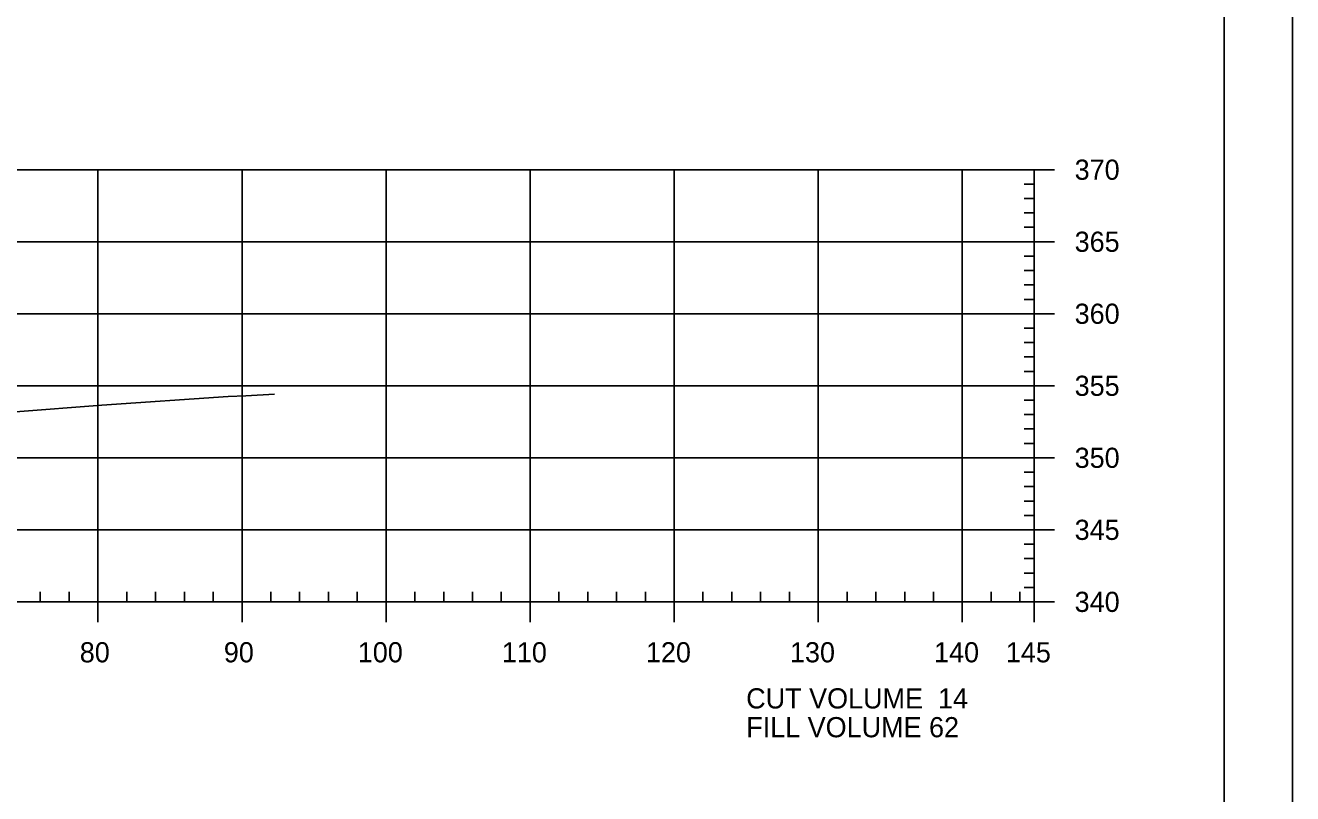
# Model space of a CAD drawing. Extents: x 1359801 to 1362404, y 372415 to 374228.
# Drawn here: x 1360662.5 to 1360750.5, y 373054.6 to 373107.9 of the extents above; entities that cross this region are included whole.
import ezdxf

# ---------------------------------------------------------------- set-up
doc = ezdxf.new("R2010")
doc.units = 0
for name, color, linetype in [('S_DRG_PT_SYM', 7, 'Continuous'), ('S_MAILBOX', 7, 'Continuous'), ('S_PRIMARY_CTL', 7, 'Continuous'), ('S_SHOULDER', 7, 'Continuous'), ('S_UTL_PT_SYM', 7, 'Continuous'), ('S_WATER_UTILITIES', 7, 'Continuous')]:
    doc.layers.add(name, color=color, linetype=linetype)

msp = doc.modelspace()

# ---------------------------------------------------------------- linework, layer by layer
at = {"layer": 'S_DRG_PT_SYM'}
msp.add_lwpolyline([(1360609.474, 373085.356), (1360612.579, 373085.454), (1360613.429, 373085.483), (1360615.592, 373085.51), (1360623.736, 373085.611), (1360633.045, 373085.497), (1360634.465, 373085.481), (1360634.829, 373085.474), (1360637.443, 373085.413), (1360640.348, 373085.109), (1360640.641, 373085.041), (1360640.953, 373085.008), (1360645.028, 373083.336), (1360650.394, 373080.847), (1360656.347, 373078.113), (1360658.498, 373079.317), (1360661.816, 373081.124), (1360667.793, 373081.578), (1360676.568, 373082.174), (1360677.799, 373082.228), (1360679.788, 373082.347)], dxfattribs=at)
at = {"layer": 'S_MAILBOX'}
for p, q in [((1360442.53, 373097.922), (1360732.53, 373097.922)), ((1360667.53, 373067.922), (1360667.53, 373097.922)), ((1360677.53, 373067.922), (1360677.53, 373097.922)), ((1360687.53, 373067.922), (1360687.53, 373097.922)), ((1360697.53, 373067.922), (1360697.53, 373097.922)), ((1360707.53, 373067.922), (1360707.53, 373097.922)), ((1360717.53, 373067.922), (1360717.53, 373097.922)), ((1360727.53, 373067.922), (1360727.53, 373097.922)), ((1360732.53, 373067.922), (1360732.53, 373097.922)), ((1360442.53, 373092.922), (1360732.53, 373092.922)), ((1360442.53, 373087.922), (1360732.53, 373087.922)), ((1360442.53, 373082.922), (1360732.53, 373082.922)), ((1360442.53, 373077.922), (1360732.53, 373077.922)), ((1360442.53, 373072.922), (1360732.53, 373072.922)), ((1360442.53, 373067.922), (1360732.53, 373067.922))]:
    msp.add_line(p, q, dxfattribs=at)
at = {"layer": 'S_SHOULDER'}
for points in [[(1360417.123, 373161.276), (1360750.463, 373161.276), (1360750.463, 372947.939), (1360417.123, 372947.939)], [(1360663.45, 373157.382), (1360663.45, 373147.502), (1360699.182, 373147.502), (1360699.182, 373144.582), (1360722.382, 373144.582), (1360722.382, 373120.249), (1360745.71, 373120.249), (1360745.71, 372951.922), (1360429.53, 372951.922), (1360429.53, 373157.382)]]:
    msp.add_lwpolyline(points, close=True, dxfattribs=at)
at = {"layer": 'S_UTL_PT_SYM'}
msp.add_line((1360745.71, 372951.922), (1360745.71, 373157.382), dxfattribs=at)
at = {"layer": 'S_WATER_UTILITIES'}
for p, q in [((1360732.53, 373067.922), (1360732.53, 373097.922)), ((1360733.93, 373097.922), (1360732.53, 373097.922)), ((1360732.53, 373096.922), (1360731.83, 373096.922)), ((1360732.53, 373095.922), (1360731.83, 373095.922)), ((1360732.53, 373094.922), (1360731.83, 373094.922)), ((1360732.53, 373093.922), (1360731.83, 373093.922)), ((1360733.93, 373092.922), (1360732.53, 373092.922)), ((1360732.53, 373091.922), (1360731.83, 373091.922)), ((1360732.53, 373090.922), (1360731.83, 373090.922)), ((1360732.53, 373089.922), (1360731.83, 373089.922)), ((1360732.53, 373088.922), (1360731.83, 373088.922)), ((1360733.93, 373087.922), (1360732.53, 373087.922)), ((1360732.53, 373086.922), (1360731.83, 373086.922)), ((1360732.53, 373085.922), (1360731.83, 373085.922)), ((1360732.53, 373084.922), (1360731.83, 373084.922)), ((1360732.53, 373083.922), (1360731.83, 373083.922)), ((1360733.93, 373082.922), (1360732.53, 373082.922)), ((1360732.53, 373081.922), (1360731.83, 373081.922)), ((1360732.53, 373080.922), (1360731.83, 373080.922)), ((1360732.53, 373079.922), (1360731.83, 373079.922)), ((1360732.53, 373078.922), (1360731.83, 373078.922)), ((1360733.93, 373077.922), (1360732.53, 373077.922)), ((1360732.53, 373076.922), (1360731.83, 373076.922)), ((1360732.53, 373075.922), (1360731.83, 373075.922)), ((1360732.53, 373074.922), (1360731.83, 373074.922)), ((1360732.53, 373073.922), (1360731.83, 373073.922)), ((1360733.93, 373072.922), (1360732.53, 373072.922)), ((1360732.53, 373071.922), (1360731.83, 373071.922)), ((1360732.53, 373070.922), (1360731.83, 373070.922)), ((1360732.53, 373069.922), (1360731.83, 373069.922)), ((1360663.53, 373067.922), (1360663.53, 373068.622)), ((1360665.53, 373067.922), (1360665.53, 373068.622)), ((1360669.53, 373067.922), (1360669.53, 373068.622)), ((1360671.53, 373067.922), (1360671.53, 373068.622)), ((1360673.53, 373067.922), (1360673.53, 373068.622)), ((1360675.53, 373067.922), (1360675.53, 373068.622)), ((1360679.53, 373067.922), (1360679.53, 373068.622)), ((1360681.53, 373067.922), (1360681.53, 373068.622)), ((1360683.53, 373067.922), (1360683.53, 373068.622)), ((1360685.53, 373067.922), (1360685.53, 373068.622)), ((1360689.53, 373067.922), (1360689.53, 373068.622)), ((1360691.53, 373067.922), (1360691.53, 373068.622)), ((1360693.53, 373067.922), (1360693.53, 373068.622)), ((1360695.53, 373067.922), (1360695.53, 373068.622)), ((1360699.53, 373067.922), (1360699.53, 373068.622)), ((1360701.53, 373067.922), (1360701.53, 373068.622)), ((1360703.53, 373067.922), (1360703.53, 373068.622)), ((1360705.53, 373067.922), (1360705.53, 373068.622)), ((1360709.53, 373067.922), (1360709.53, 373068.622)), ((1360711.53, 373067.922), (1360711.53, 373068.622)), ((1360713.53, 373067.922), (1360713.53, 373068.622)), ((1360715.53, 373067.922), (1360715.53, 373068.622)), ((1360719.53, 373067.922), (1360719.53, 373068.622)), ((1360721.53, 373067.922), (1360721.53, 373068.622)), ((1360723.53, 373067.922), (1360723.53, 373068.622)), ((1360725.53, 373067.922), (1360725.53, 373068.622)), ((1360729.53, 373067.922), (1360729.53, 373068.622)), ((1360731.53, 373067.922), (1360731.53, 373068.622)), ((1360732.53, 373068.922), (1360731.83, 373068.922)), ((1360442.53, 373067.922), (1360732.53, 373067.922)), ((1360667.53, 373066.522), (1360667.53, 373067.922)), ((1360677.53, 373066.522), (1360677.53, 373067.922)), ((1360687.53, 373066.522), (1360687.53, 373067.922)), ((1360697.53, 373066.522), (1360697.53, 373067.922)), ((1360707.53, 373066.522), (1360707.53, 373067.922)), ((1360717.53, 373066.522), (1360717.53, 373067.922)), ((1360727.53, 373066.522), (1360727.53, 373067.922)), ((1360732.53, 373066.522), (1360732.53, 373067.922)), ((1360733.93, 373067.922), (1360732.53, 373067.922))]:
    msp.add_line(p, q, dxfattribs=at)

# ---------------------------------------------------------------- texts
at = {"layer": 'S_PRIMARY_CTL'}
for s, p in [('370', (1360735.33, 373097.222)), ('365', (1360735.33, 373092.222)), ('360', (1360735.33, 373087.222)), ('355', (1360735.33, 373082.222)), ('350', (1360735.33, 373077.222)), ('345', (1360735.33, 373072.222)), ('340', (1360735.33, 373067.222)), ('80', (1360666.269, 373063.722)), ('90', (1360676.269, 373063.722)), ('100', (1360685.569, 373063.722)), ('110', (1360695.569, 373063.722)), ('120', (1360705.569, 373063.722)), ('130', (1360715.569, 373063.722)), ('140', (1360725.569, 373063.722)), ('145', (1360730.556, 373063.722)), ('CUT VOLUME  14', (1360712.53, 373060.522)), ('FILL VOLUME 62', (1360712.53, 373058.522))]:
    msp.add_text(s, height=1.4, dxfattribs=at).set_placement(p)

doc.saveas('drawing.dxf')
